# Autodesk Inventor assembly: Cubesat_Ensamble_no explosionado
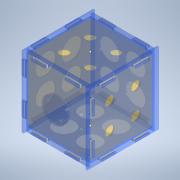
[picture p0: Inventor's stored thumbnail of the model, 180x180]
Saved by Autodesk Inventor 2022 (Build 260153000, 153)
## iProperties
Created: 2022-05
Part Number: Cubesat_Ensamble_no explosionado
Document SubType Name: Assembly
Designer: valen
Author: valen
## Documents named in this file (11)
- C:\Users\valen\Desktop\Estandar CubeSat - Programa AVES-20220531T050024Z-001\Estandar CubeSat - Programa AVES\3D - MODELS\Cubesat_Ensamble_no explosionado.iam
- C:\Users\valen\Desktop\Estandar CubeSat - Programa AVES-20220531T050024Z-001\Estandar CubeSat - Programa AVES\3D - MODELS\Volumen interno .ipt
- C:\Users\valen\Desktop\Estandar CubeSat - Programa AVES-20220531T050024Z-001\Estandar CubeSat - Programa AVES\3D - MODELS\1.Frontal.ipt
- C:\Users\valen\Desktop\Estandar CubeSat - Programa AVES-20220531T050024Z-001\Estandar CubeSat - Programa AVES\3D - MODELS\3.Posterior.ipt
- C:\Users\valen\Desktop\Estandar CubeSat - Programa AVES-20220531T050024Z-001\Estandar CubeSat - Programa AVES\3D - MODELS\2.Lateral derecha .ipt
- C:\Users\valen\Desktop\Estandar CubeSat - Programa AVES-20220531T050024Z-001\Estandar CubeSat - Programa AVES\3D - MODELS\4.Lateral izquierda.ipt
- C:\Users\valen\Desktop\Estandar CubeSat - Programa AVES-20220531T050024Z-001\Estandar CubeSat - Programa AVES\3D - MODELS\6.Inferior.ipt
- C:\Users\valen\Desktop\Estandar CubeSat - Programa AVES-20220531T050024Z-001\Estandar CubeSat - Programa AVES\3D - MODELS\5.Superior.ipt
- C:\Users\valen\Desktop\Estandar CubeSat - Programa AVES-20220531T050024Z-001\Estandar CubeSat - Programa AVES\3D - MODELS\7. Arandela.ipt
- C:\Users\valen\Desktop\Estandar CubeSat - Programa AVES-20220531T050024Z-001\Estandar CubeSat - Programa AVES\3D - MODELS\8. Soporte tuercas.ipt
- C:\Users\valen\Desktop\Estandar CubeSat - Programa AVES-20220531T050024Z-001\Estandar CubeSat - Programa AVES\3D - MODELS\Oring.ipt
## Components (29 placed, 10 different names)
1. Volumen interno :1 — Flush:1, Mate:1, Flush:2, Flush:3, Flush:4, Mate:2, Flush:5, Mate:3, Mate:4, Mate:5, Mate:6, Mate:7, Flush:7, Flush:8, Mate:8, Flush:9
2. 1.Frontal:1 — Flush:1, Mate:1, Flush:3, Flush:10, Mate:16, Mate:18, Mate:20, Mate:22, Mate:24
3. 6.Inferior:1 — Flush:7, Flush:8, Mate:8, Mate:11, Mate:12, Mate:13, Mate:19, Flush:12, Mate:21, Flush:13, Mate:31, Flush:18, Mate:33, Flush:19, Mate:46, Mate:48, Mate:50, Mate:52
4. 3.Posterior:1 — Flush:4, Mate:2, Flush:5, Mate:26, Mate:28, Mate:30, Mate:32, Mate:34, Mate:36
5. 2.Lateral derecha :1 — Mate:3, Mate:4, Mate:5, Flush:6, Mate:23, Flush:14, Mate:25, Flush:15, Mate:27, Flush:16, Mate:29, Flush:17, Mate:39, Flush:22, Mate:41, Flush:23, Mate:47, Flush:26, Mate:49, Flush:27
6. 4.Lateral izquierda:1 — Mate:6, Mate:7, Flush:6, Mate:17, Flush:11, Mate:35, Flush:20, Mate:37, Flush:21, Mate:43, Flush:24, Mate:45, Flush:25, Mate:51, Flush:28, Mate:53, Flush:29
7. 5.Superior:1 — Flush:9, Mate:38, Mate:40, Mate:42, Mate:44
8. 7. Arandela:1 — Mate:11, Mate:12, Mate:13, Mate:14, Mate:15
9. 8. Soporte tuercas:1 — Mate:14, Mate:15
10. Oring:1 — Flush:10
11. Oring:2 — Mate:16, Mate:17, Flush:11
12. Oring:3 — Mate:18, Mate:19, Flush:12
13. Oring:4 — Mate:20, Mate:21, Flush:13
14. Oring:5 — Mate:22, Mate:23, Flush:14
15. Oring:6 — Mate:24, Mate:25, Flush:15
16. Oring:7 — Mate:26, Mate:27, Flush:16
17. Oring:8 — Mate:36, Mate:37, Flush:21
18. Oring:9 — Mate:32, Mate:33, Flush:19
19. Oring:10 — Mate:34, Mate:35, Flush:20
20. Oring:11 — Mate:30, Mate:31, Flush:18
21. Oring:12 — Mate:28, Mate:29, Flush:17
22. Oring:13 — Mate:40, Mate:41, Flush:23
23. Oring:14 — Mate:42, Mate:43, Flush:24
24. Oring:15 — Mate:38, Mate:39, Flush:22
25. Oring:16 — Mate:44, Mate:45, Flush:25
26. Oring:17 — Mate:48, Mate:49, Flush:27
27. Oring:18 — Mate:46, Mate:47, Flush:26
28. Oring:19 — Mate:52, Mate:53, Flush:29
29. Oring:20 — Mate:50, Mate:51, Flush:28
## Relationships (80: Mate 51, Flush 29)
- Flush:1: Volumen interno :1 ↔ 1.Frontal:1
- Mate:1: Volumen interno :1 ↔ 1.Frontal:1
- Flush:2: Volumen interno :1
- Flush:3: Volumen interno :1 ↔ 1.Frontal:1
- Flush:4: Volumen interno :1 ↔ 3.Posterior:1
- Mate:2: Volumen interno :1 ↔ 3.Posterior:1
- Flush:5: Volumen interno :1 ↔ 3.Posterior:1
- Mate:3: Volumen interno :1 ↔ 2.Lateral derecha :1
- Mate:4: Volumen interno :1 ↔ 2.Lateral derecha :1
- Mate:5: Volumen interno :1 ↔ 2.Lateral derecha :1
- Mate:6: Volumen interno :1 ↔ 4.Lateral izquierda:1
- Mate:7: Volumen interno :1 ↔ 4.Lateral izquierda:1
- Flush:6: 2.Lateral derecha :1 ↔ 4.Lateral izquierda:1
- Flush:7: Volumen interno :1 ↔ 6.Inferior:1
- Flush:8: Volumen interno :1 ↔ 6.Inferior:1
- Mate:8: Volumen interno :1 ↔ 6.Inferior:1
- Flush:9: Volumen interno :1 ↔ 5.Superior:1
- Mate:11: 6.Inferior:1 ↔ 7. Arandela:1
- Mate:12: 6.Inferior:1 ↔ 7. Arandela:1
- Mate:13: 6.Inferior:1 ↔ 7. Arandela:1
- Mate:14: 7. Arandela:1 ↔ 8. Soporte tuercas:1
- Mate:15: 7. Arandela:1 ↔ 8. Soporte tuercas:1
- Flush:10: 1.Frontal:1 ↔ Oring:1
- Mate:16: 1.Frontal:1 ↔ Oring:2
- Mate:17: 4.Lateral izquierda:1 ↔ Oring:2
- Flush:11: 4.Lateral izquierda:1 ↔ Oring:2
- Mate:18: 1.Frontal:1 ↔ Oring:3
- Mate:19: 6.Inferior:1 ↔ Oring:3
- Flush:12: 6.Inferior:1 ↔ Oring:3
- Mate:20: 1.Frontal:1 ↔ Oring:4
- Mate:21: 6.Inferior:1 ↔ Oring:4
- Flush:13: 6.Inferior:1 ↔ Oring:4
- Mate:22: 1.Frontal:1 ↔ Oring:5
- Mate:23: 2.Lateral derecha :1 ↔ Oring:5
- Flush:14: 2.Lateral derecha :1 ↔ Oring:5
- Mate:24: 1.Frontal:1 ↔ Oring:6
- Mate:25: 2.Lateral derecha :1 ↔ Oring:6
- Flush:15: 2.Lateral derecha :1 ↔ Oring:6
- Mate:26: 3.Posterior:1 ↔ Oring:7
- Mate:27: 2.Lateral derecha :1 ↔ Oring:7
- Flush:16: 2.Lateral derecha :1 ↔ Oring:7
- Mate:28: 3.Posterior:1 ↔ Oring:12
- Mate:29: 2.Lateral derecha :1 ↔ Oring:12
- Flush:17: 2.Lateral derecha :1 ↔ Oring:12
- Mate:30: 3.Posterior:1 ↔ Oring:11
- Mate:31: 6.Inferior:1 ↔ Oring:11
- Flush:18: 6.Inferior:1 ↔ Oring:11
- Mate:32: 3.Posterior:1 ↔ Oring:9
- Mate:33: 6.Inferior:1 ↔ Oring:9
- Flush:19: 6.Inferior:1 ↔ Oring:9
- Mate:34: 3.Posterior:1 ↔ Oring:10
- Mate:35: 4.Lateral izquierda:1 ↔ Oring:10
- Flush:20: 4.Lateral izquierda:1 ↔ Oring:10
- Mate:36: 3.Posterior:1 ↔ Oring:8
- Mate:37: 4.Lateral izquierda:1 ↔ Oring:8
- Flush:21: 4.Lateral izquierda:1 ↔ Oring:8
- Mate:38: 5.Superior:1 ↔ Oring:15
- Mate:39: 2.Lateral derecha :1 ↔ Oring:15
- Flush:22: 2.Lateral derecha :1 ↔ Oring:15
- Mate:40: 5.Superior:1 ↔ Oring:13
- Mate:41: 2.Lateral derecha :1 ↔ Oring:13
- Flush:23: 2.Lateral derecha :1 ↔ Oring:13
- Mate:42: 5.Superior:1 ↔ Oring:14
- Mate:43: 4.Lateral izquierda:1 ↔ Oring:14
- Flush:24: 4.Lateral izquierda:1 ↔ Oring:14
- Mate:44: 5.Superior:1 ↔ Oring:16
- Mate:45: 4.Lateral izquierda:1 ↔ Oring:16
- Flush:25: 4.Lateral izquierda:1 ↔ Oring:16
- Mate:46: 6.Inferior:1 ↔ Oring:18
- Mate:47: 2.Lateral derecha :1 ↔ Oring:18
- Flush:26: 2.Lateral derecha :1 ↔ Oring:18
- Mate:48: 6.Inferior:1 ↔ Oring:17
- Mate:49: 2.Lateral derecha :1 ↔ Oring:17
- Flush:27: 2.Lateral derecha :1 ↔ Oring:17
- Mate:50: 6.Inferior:1 ↔ Oring:20
- Mate:51: 4.Lateral izquierda:1 ↔ Oring:20
- Flush:28: 4.Lateral izquierda:1 ↔ Oring:20
- Mate:52: 6.Inferior:1 ↔ Oring:19
- Mate:53: 4.Lateral izquierda:1 ↔ Oring:19
- Flush:29: 4.Lateral izquierda:1 ↔ Oring:19
